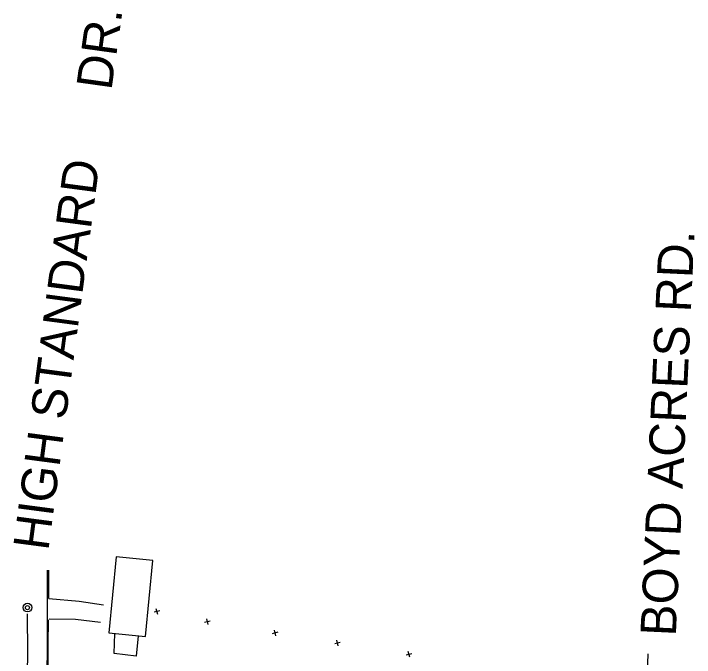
# Model space of a CAD drawing. Extents: x 4711259 to 4716401, y 890074 to 892728.
# Drawn here: x 4714378 to 4714969, y 891674 to 892234 of the extents above; entities that cross this region are included whole.
import ezdxf

# ---------------------------------------------------------------- set-up
doc = ezdxf.new("R2010")
doc.units = 0
for name, color, linetype in [('E_HY_STORM_MH', 7, 'Continuous'), ('E_RDWY_PHOTOG_Eave', 7, 'Continuous'), ('E_RDWY_ROAD_Curb', 7, 'Continuous'), ('E_RDWY_ROAD_EdgeAsph', 7, 'Continuous'), ('E_RDWY_ROAD_NameTx', 7, 'Continuous'), ('E_RDWY_ROAD_TBofCurb', 7, 'Continuous'), ('E_TERR_DTM_BrkLines', 7, 'Continuous'), ('E_TERR_DTM_RandomPt', 7, 'Continuous')]:
    doc.layers.add(name, color=color, linetype=linetype)

msp = doc.modelspace()

# ---------------------------------------------------------------- linework, layer by layer
at = {"layer": 'E_HY_STORM_MH'}
for radius in [3.75, 1.76]:
    msp.add_circle((4714389.99, 891717.66), radius, dxfattribs=at)
at = {"layer": 'E_RDWY_PHOTOG_Eave'}
msp.add_lwpolyline([(4714492.62, 891692.69), (4714498.93, 891758.66), (4714467.01, 891761.71), (4714460.7, 891695.75)], close=True, dxfattribs=at)
msp.add_lwpolyline([(4714486.14, 891693.15), (4714484.56, 891675.62), (4714465.46, 891677.74), (4714465.92, 891695.05)], dxfattribs=at)
at = {"layer": 'E_RDWY_ROAD_Curb'}
msp.add_lwpolyline([(4714406.94, 891630.31), (4714407.29, 891685.99), (4714407.32, 891707.16), (4714407.34, 891709.72), (4714407.35, 891724.91), (4714407.42, 891727.85), (4714407.53, 891750.34)], dxfattribs=at)
at = {"layer": 'E_RDWY_ROAD_EdgeAsph'}
for points in [[(4714456.1, 891719.67), (4714435.03, 891723.03), (4714408.57, 891725.32)], [(4714408.73, 891707.85), (4714431.85, 891707.57), (4714453.49, 891705.06)], [(4714928.91, 891677.41), (4714927.35, 891627.44), (4714926.44, 891566.8), (4714921.46, 891514.05), (4714910.32, 891470.49), (4714895.76, 891428.7), (4714878.11, 891394.18), (4714864.84, 891368.83), (4714860.55, 891364.18), (4714841.33, 891355.8), (4714793.66, 891360.05), (4714747.59, 891363.54), (4714683.67, 891364.81), (4714630.51, 891365.23), (4714572.54, 891365.83), (4714518.44, 891365.84), (4714463.12, 891365.94), (4714435.29, 891366.09), (4714417.84, 891368.4), (4714409.72, 891374.94)]]:
    msp.add_lwpolyline(points, dxfattribs=at)
at = {"layer": 'E_RDWY_ROAD_TBofCurb'}
for points in [[(4714408.24, 891750.24), (4714408.15, 891727.84)], [(4714408.37, 891750.07), (4714408.31, 891725.65)], [(4714408, 891707.18), (4714407.82, 891685.93), (4714407.6, 891652.58), (4714407.56, 891630.14), (4714407.33, 891598.72), (4714407.29, 891571.32), (4714411.62, 891561.94), (4714422.61, 891558.04), (4714433.51, 891558.02), (4714490.31, 891557.78), (4714500.83, 891560.36), (4714512.66, 891569.93)]]:
    msp.add_lwpolyline(points, dxfattribs=at)
at = {"layer": 'E_TERR_DTM_BrkLines'}
msp.add_lwpolyline([(4714388.98, 891381.46), (4714389.18, 891412.24), (4714388.56, 891455.05), (4714388.86, 891495.74), (4714389.44, 891520.88), (4714389.73, 891568.87), (4714389.47, 891628.36), (4714390.44, 891677.73), (4714389.95, 891712.3)], dxfattribs=at)
at = {"layer": 'E_TERR_DTM_RandomPt'}
for p, q in [((4714504.99, 891714.89), (4714500.15, 891713.64)), ((4714503.2, 891711.84), (4714501.95, 891716.68)), ((4714546.94, 891702.98), (4714545.69, 891707.82)), ((4714548.74, 891706.02), (4714543.9, 891704.77)), ((4714607.54, 891696.29), (4714602.7, 891695.04)), ((4714605.75, 891693.25), (4714604.5, 891698.09)), ((4714660, 891684.45), (4714658.75, 891689.29)), ((4714661.8, 891687.49), (4714656.95, 891686.24)), ((4714723.88, 891677.67), (4714719.04, 891676.42)), ((4714722.09, 891674.63), (4714720.84, 891679.47))]:
    msp.add_line(p, q, dxfattribs=at)

# ---------------------------------------------------------------- texts
at = {"layer": 'E_RDWY_ROAD_NameTx'}
for s, height, rotation, p in [('DR.', 30.84, 82.07033, (4714462.9, 892166.53)), ('HIGH STANDARD', 30.8399, 82.46717, (4714408.1, 891766.53)), ('BOYD ACRES RD.', 30.8399, 87.34739, (4714953.25, 891692.38))]:
    msp.add_text(s, height=height, rotation=rotation, dxfattribs=at).set_placement(p)

doc.saveas('drawing.dxf')
